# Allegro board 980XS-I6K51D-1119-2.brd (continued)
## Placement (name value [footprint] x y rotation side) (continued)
NOREF#777  -  []  348.03 289.54 0 top
NOREF#778  -  []  351.69 209.1 0 top
NOREF#779  -  []  457.43 161.06 0 top
NOREF#780  -  []  353.8 243.65 0 top
NOREF#781  -  []  481.73 253.51 0 top
NOREF#782  -  []  373.62 484.08 0 top
NOREF#783  -  []  100.39 154.45 0 top
NOREF#784  -  []  267.55 484.08 0 top
NOREF#785  -  []  223.27 174.06 0 top
NOREF#786  -  []  300.62 297.29 0 top
NOREF#787  -  []  332.33 182.3 90 top
NOREF#788  -  []  487.59 137.63 90 top
NOREF#789  -  []  227 259.15 0 top
NOREF#790  -  []  309.17 178.73 90 top
NOREF#791  -  []  479.53 221.76 0 top
NOREF#792  -  []  535.13 205.77 90 top
NOREF#793  -  []  350.87 210.03 90 top
NOREF#794  -  []  213.61 182 0 top
NOREF#795  -  []  352.23 230.19 90 top
NOREF#796  -  []  524.36 233.84 90 top
NOREF#797  -  []  474.48 169.9 0 top
NOREF#798  -  []  229.5 210 0 top
NOREF#799  -  []  226.84 148.23 90 top
NOREF#800  -  []  459.73 192.01 0 top
NOREF#801  -  []  232.7 190.05 0 top
NOREF#802  -  []  85 291.64 0 top
NOREF#803  -  []  309.83 269.1 90 top
NOREF#804  -  []  78.8 264.19 0 top
NOREF#805  -  []  304.91 233.9 0 top
NOREF#806  -  []  228.09 268.12 0 top
NOREF#807  -  []  310.5 190.23 90 top
NOREF#808  -  []  403.55 467.68 0 top
NOREF#809  -  []  223.09 172.9 0 top
NOREF#810  -  []  227.05 134.86 0 top
NOREF#811  -  []  210.61 235.6 90 top
NOREF#812  -  []  300.15 483.75 90 top
NOREF#813  -  []  99.29 220.75 0 top
NOREF#814  -  []  48.53 250.3 0 top
NOREF#815  -  []  275.44 194.76 90 top
NOREF#816  -  []  237.14 138.77 90 top
NOREF#817  -  []  490.86 199.63 90 top
NOREF#818  -  []  343.95 173.9 90 top
NOREF#819  -  []  349.53 181.46 90 top
NOREF#820  -  []  223.09 233.82 0 top
NOREF#821  -  []  311.8 250.23 90 top
NOREF#822  -  []  292.33 253.86 90 top
NOREF#823  -  []  393.34 467.08 0 top
NOREF#824  -  []  311.78 243.92 90 top
NOREF#825  -  []  310.92 244.4 0 top
NOREF#826  -  []  211.34 254.86 0 top
NOREF#827  -  []  122.2 484.32 0 top
NOREF#828  -  []  285.83 229.63 90 top
NOREF#829  -  []  540.03 233.63 90 top
NOREF#830  -  []  488.26 212.68 90 top
NOREF#831  -  []  262.45 231.5 0 top
NOREF#832  -  []  342.49 297.25 90 top
NOREF#833  -  []  349.53 240.81 90 top
NOREF#834  -  []  315.12 299.54 0 top
NOREF#835  -  []  260.96 235.55 90 top
NOREF#836  -  []  559.34 167.08 0 top
NOREF#837  -  []  345.33 135.72 0 top
NOREF#838  -  []  302.22 296.45 90 top
NOREF#839  -  []  317.44 253.76 90 top
NOREF#840  -  []  269.83 209.1 90 top
NOREF#841  -  []  458.53 190.01 0 top
NOREF#842  -  []  462.89 201.02 90 top
NOREF#843  -  []  273.49 295.27 90 top
NOREF#844  -  []  278.28 483.75 90 top
NOREF#845  -  []  292.33 182.3 90 top
NOREF#846  -  []  130.08 483.84 90 top
NOREF#847  -  []  481.53 160.91 90 top
NOREF#848  -  []  487.26 226.78 90 top
NOREF#849  -  []  37.98 484.08 0 top
NOREF#850  -  []  474.48 233.4 0 top
NOREF#851  -  []  313.4 298.37 0 top
NOREF#852  -  []  232.91 249.57 90 top
NOREF#853  -  []  142.1 483.84 90 top
NOREF#854  -  []  381.98 467.63 0 top
NOREF#855  -  []  310.87 210.03 90 top
NOREF#856  -  []  295.56 192.47 90 top
NOREF#857  -  []  356.15 189.57 90 top
NOREF#858  -  []  271.03 245.37 0 top
NOREF#859  -  []  279.68 483.76 90 top
NOREF#860  -  []  293.39 183.61 0 top
NOREF#861  -  []  468.26 170.15 0 top
NOREF#862  -  []  294.36 181.55 0 top
NOREF#863  -  []  270.16 244.72 90 top
NOREF#864  -  []  270.62 187.15 0 top
NOREF#865  -  []  226.61 190.23 90 top
NOREF#866  -  []  233.49 295.27 90 top
NOREF#867  -  []  230.75 241.59 0 top
NOREF#868  -  []  344.52 288.97 0 top
NOREF#869  -  []  356.89 133.69 0 top
NOREF#870  -  []  28.16 484.08 0 top
NOREF#871  -  []  148.26 484.32 0 top
NOREF#872  -  []  335.71 192.27 0 top
NOREF#873  -  []  227.71 189.57 90 top
NOREF#874  -  []  214.36 243.2 0 top
NOREF#875  -  []  291.83 230.23 315 top
NOREF#876  -  []  332.78 190.69 90 top
NOREF#877  -  []  265.48 235.27 0 top
NOREF#878  -  []  120.26 483.84 90 top
NOREF#879  -  []  362.33 173.13 90 top
NOREF#880  -  []  307.03 241.43 90 top
NOREF#881  -  []  215.56 252.47 90 top
NOREF#882  -  []  316.16 189.57 90 top
NOREF#883  -  []  268.52 244.61 90 top
NOREF#884  -  []  315.13 183 0 top
NOREF#885  -  []  254.3 250.94 90 top
NOREF#886  -  []  316.09 484.08 0 top
NOREF#887  -  []  476.48 161.06 0 top
NOREF#888  -  []  256.21 252.91 90 top
NOREF#889  -  []  242.3 484.08 0 top
NOREF#890  -  []  142.83 484.08 0 top
NOREF#891  -  []  272.25 189.57 90 top
NOREF#892  -  []  476.48 161.06 0 top
NOREF#893  -  []  527.08 484.08 0 top
NOREF#894  -  []  104.66 193.9 0 top
NOREF#895  -  []  261.29 297.9 0 top
NOREF#896  -  []  473.18 190.01 0 top
NOREF#897  -  []  227.03 241.43 90 top
NOREF#898  -  []  280.05 484.32 0 top
NOREF#899  -  []  254.38 183.29 0 top
NOREF#900  -  []  482.26 163.28 0 top
NOREF#901  -  []  269.11 232.64 90 top
NOREF#902  -  []  240.12 259.78 0 top
NOREF#903  -  []  294.68 195.18 0 top
NOREF#904  -  []  254.42 178.17 90 top
NOREF#905  -  []  87.37 286.27 90 top
NOREF#906  -  []  40.23 254.72 0 top
NOREF#907  -  []  253.61 242 0 top
NOREF#908  -  []  294.68 242.3 90 top
NOREF#909  -  []  347.56 144.79 0 top
NOREF#910  -  []  106.74 249.7 0 top
NOREF#911  -  []  351.48 186.02 90 top
NOREF#912  -  []  508.12 207 90 top
NOREF#913  -  []  305.97 484.4 0 top
NOREF#914  -  []  547.34 221.28 0 top
NOREF#915  -  []  231.03 185.37 0 top
NOREF#916  -  []  566.42 171.11 0 top
NOREF#917  -  []  353.17 296.17 0 top
NOREF#918  -  []  275.47 483.75 90 top
NOREF#919  -  []  138.62 484.08 0 top
NOREF#920  -  []  86.59 252.5 0 top
NOREF#921  -  []  254.3 179.37 90 top
NOREF#922  -  []  352.27 484.4 0 top
NOREF#923  -  []  211.16 191.72 0 top
NOREF#924  -  []  495.12 208.21 90 top
NOREF#925  -  []  335.23 483.75 90 top
NOREF#926  -  []  255.83 259.63 0 top
NOREF#927  -  []  275.81 182.28 90 top
NOREF#928  -  []  331.83 170.23 315 top
NOREF#929  -  []  381.68 462.53 90 top
NOREF#930  -  []  228.03 292.21 0 top
NOREF#931  -  []  104.34 252.35 90 top
NOREF#932  -  []  348.93 268.11 0 top
NOREF#933  -  []  215.71 242 90 top
NOREF#934  -  []  231.21 185.61 0 top
NOREF#935  -  []  331.64 243.61 0 top
NOREF#936  -  []  268.55 238.53 90 top
NOREF#937  -  []  347.9 182.43 90 top
NOREF#938  -  []  371.73 466.58 90 top
NOREF#939  -  []  122.38 484.08 0 top
NOREF#940  -  []  235.06 190.23 90 top
NOREF#941  -  []  291.83 170.23 315 top
NOREF#942  -  []  257.83 192.37 0 top
NOREF#943  -  []  289.83 225.63 90 top
NOREF#944  -  []  291.23 236.59 90 top
NOREF#945  -  []  475.5 134.21 0 top
NOREF#946  -  []  298.17 269.61 90 top
NOREF#947  -  []  232.57 246.5 0 top
NOREF#948  -  []  230.59 244.96 0 top
NOREF#949  -  []  110.89 186.2 0 top
NOREF#950  -  []  309.94 186.91 0 top
NOREF#951  -  []  344.96 136.11 90 top
NOREF#952  -  []  475.5 197.71 0 top
NOREF#953  -  []  488.26 244.43 90 top
NOREF#954  -  []  344.16 467.63 0 top
NOREF#955  -  []  83.29 217.95 0 top
NOREF#956  -  []  52.02 484.08 0 top
NOREF#957  -  []  354.92 467.68 0 top
NOREF#958  -  []  451.08 161.06 0 top
NOREF#959  -  []  235.44 194.76 90 top
NOREF#960  -  []  231.16 246.31 90 top
NOREF#961  -  []  349.26 462.53 90 top
NOREF#962  -  []  534.61 231.63 0 top
NOREF#963  -  []  134.41 484.08 0 top
NOREF#964  -  []  335.49 243.29 90 top
NOREF#965  -  []  255.1 274.12 0 top
NOREF#966  -  []  511.12 227.17 90 top
NOREF#967  -  []  212.96 243.2 0 top
NOREF#968  -  []  297.55 484.4 0 top
NOREF#969  -  []  59.94 196.2 0 top
NOREF#970  -  []  334.03 484.4 0 top
NOREF#971  -  []  340.81 187.17 90 top
NOREF#972  -  []  261.62 297 90 top
NOREF#973  -  []  568.79 147.98 0 top
NOREF#974  -  []  236.59 262.58 0 top
NOREF#975  -  []  232.23 167.99 90 top
NOREF#976  -  []  215.38 253.86 90 top
NOREF#977  -  []  85.29 220.6 90 top
NOREF#978  -  []  236.11 224.14 90 top
NOREF#979  -  []  351.26 247.56 0 top
NOREF#980  -  []  111.42 222.97 0 top
NOREF#981  -  []  49.56 267.3 90 top
NOREF#982  -  []  466.83 253.51 0 top
NOREF#983  -  []  367.5 483.75 90 top
NOREF#984  -  []  161.07 484.08 0 top
NOREF#985  -  []  346.91 146.64 0 top
NOREF#986  -  []  351.8 181.77 90 top
NOREF#987  -  []  541.61 164.49 0 top
NOREF#988  -  []  334.42 249.74 90 top
NOREF#989  -  []  361.57 134.52 90 top
NOREF#990  -  []  230.92 184.4 0 top
NOREF#991  -  []  104.34 188.85 90 top
NOREF#992  -  []  335.71 242 0 top
NOREF#993  -  []  232.45 183.76 90 top
NOREF#994  -  []  95.24 251.7 0 top
NOREF#995  -  []  294.42 238.17 90 top
NOREF#996  -  []  305.94 263.76 0 top
NOREF#997  -  []  39.39 484.08 0 top
NOREF#998  -  []  295.09 266.49 0 top
NOREF#999  -  []  365.77 467.63 0 top
NOREF#1000  -  []  313.08 240.67 90 top
NOREF#1001  -  []  457.43 224.56 0 top
NOREF#1002  -  []  265.33 135.72 0 top
NOREF#1003  -  []  304.52 287.7 90 top
NOREF#1004  -  []  252.7 271.22 0 top
NOREF#1005  -  []  310.62 247.15 0 top
NOREF#1006  -  []  253.86 192.91 90 top
NOREF#1007  -  []  293.54 239.12 90 top
NOREF#1008  -  []  23.95 484.08 0 top
NOREF#1009  -  []  522.5 149.61 0 top
NOREF#1010  -  []  231.81 179.17 90 top
NOREF#1011  -  []  333.99 253.86 90 top
NOREF#1012  -  []  348.71 463.08 90 top
NOREF#1013  -  []  483.26 140.63 0 top
NOREF#1014  -  []  214.81 181.35 90 top
NOREF#1015  -  []  293.54 250.69 90 top
NOREF#1016  -  []  540.03 233.63 0 top
NOREF#1017  -  []  86.2 277.28 90 top
NOREF#1018  -  []  304.87 484.08 0 top
NOREF#1019  -  []  15.54 484.08 0 top
NOREF#1020  -  []  131.48 483.84 90 top
NOREF#1021  -  []  360.04 135.47 90 top
NOREF#1022  -  []  268.01 234.3 90 top
NOREF#1023  -  []  480.26 169.28 90 top
NOREF#1024  -  []  271.48 246.66 90 top
NOREF#1025  -  []  268.44 262.36 0 top
NOREF#1026  -  []  104.54 154.45 0 top
NOREF#1027  -  []  303.95 233.9 90 top
NOREF#1028  -  []  474.12 240.61 0 top
NOREF#1029  -  []  254.81 181.35 90 top
NOREF#1030  -  []  267.75 232.44 90 top
NOREF#1031  -  []  230.13 207.46 90 top
NOREF#1032  -  []  265.43 295.89 90 top
NOREF#1033  -  []  310.59 240.4 0 top
NOREF#1034  -  []  308.01 174.3 90 top
NOREF#1035  -  []  315.81 242.28 90 top
NOREF#1036  -  []  230.41 180.16 0 top
NOREF#1037  -  []  236.52 134.86 0 top
NOREF#1038  -  []  353.8 183.65 0 top
NOREF#1039  -  []  335.56 240.9 90 top
NOREF#1040  -  []  331.16 187.72 90 top
NOREF#1041  -  []  361.04 135.78 0 top
NOREF#1042  -  []  314.61 297.98 90 top
NOREF#1043  -  []  280.83 157.63 90 top
NOREF#1044  -  []  117.99 484.32 0 top
NOREF#1045  -  []  225.29 172.02 90 top
NOREF#1046  -  []  222.22 296.45 90 top
NOREF#1047  -  []  227.41 133.69 0 top
NOREF#1048  -  []  308.67 181.95 0 top
NOREF#1049  -  []  255.16 251.22 90 top
NOREF#1050  -  []  343.27 174.62 0 top
NOREF#1051  -  []  272.66 483.75 90 top
NOREF#1052  -  []  503.71 228 0 top
NOREF#1053  -  []  268.93 208.11 0 top
NOREF#1054  -  []  254.36 241.55 0 top
NOREF#1055  -  []  43.09 483.76 90 top
NOREF#1056  -  []  335.01 193.56 0 top
NOREF#1057  -  []  213.29 242.3 90 top
NOREF#1058  -  []  271.89 184.89 90 top
NOREF#1059  -  []  237.11 164.14 90 top
NOREF#1060  -  []  473.18 158.26 0 top
NOREF#1061  -  []  332.54 182.65 90 top
NOREF#1062  -  []  269.94 246.26 0 top
NOREF#1063  -  []  141.42 484.08 0 top
NOREF#1064  -  []  260.96 175.55 90 top
NOREF#1065  -  []  346.74 298.45 0 top
NOREF#1066  -  []  245.95 273.47 0 top
NOREF#1067  -  []  394.66 484.08 0 top
NOREF#1068  -  []  419.5 462.53 90 top
NOREF#1069  -  []  354.91 224.78 0 top
NOREF#1070  -  []  16.44 483.76 90 top
NOREF#1071  -  []  335.71 180.7 0 top
NOREF#1072  -  []  255.71 252.27 0 top
NOREF#1073  -  []  313.4 299.38 0 top
NOREF#1074  -  []  474.12 145.36 0 top
NOREF#1075  -  []  485.88 158.26 0 top
NOREF#1076  -  []  238.39 141.02 0 top
NOREF#1077  -  []  272.35 292.46 90 top
NOREF#1078  -  []  311.21 185.61 0 top
NOREF#1079  -  []  220.96 187.12 90 top
NOREF#1080  -  []  272.05 178.99 0 top
NOREF#1081  -  []  272.23 170.19 90 top
NOREF#1082  -  []  111.42 127.72 0 top
NOREF#1083  -  []  349.94 246.91 0 top
NOREF#1084  -  []  304.47 291.41 90 top
NOREF#1085  -  []  275.13 183 0 top
NOREF#1086  -  []  83.67 262.04 0 top
NOREF#1087  -  []  227.99 241.7 0 top
NOREF#1088  -  []  270.5 190.23 90 top
NOREF#1089  -  []  231.11 296.5 90 top
NOREF#1090  -  []  295.83 199.63 0 top
NOREF#1091  -  []  232.05 238.99 0 top
NOREF#1092  -  []  335.58 242.65 90 top
NOREF#1093  -  []  317.14 138.77 90 top
NOREF#1094  -  []  276.11 224.14 90 top
NOREF#1095  -  []  359.1 142.99 90 top
NOREF#1096  -  []  110.69 252.35 90 top
NOREF#1097  -  []  223.27 234.06 0 top
NOREF#1098  -  []  295.83 259.63 0 top
NOREF#1099  -  []  352.57 184.24 90 top
NOREF#1100  -  []  457.43 161.06 0 top
NOREF#1101  -  []  280.04 140.12 0 top
NOREF#1102  -  []  358.39 141.02 0 top
NOREF#1103  -  []  232.8 247.31 90 top
NOREF#1104  -  []  306.54 134.31 90 top
NOREF#1105  -  []  304.36 483.75 90 top
NOREF#1106  -  []  352.9 189.57 90 top
NOREF#1107  -  []  349.23 268.44 0 top
NOREF#1108  -  []  332.78 239.12 90 top
NOREF#1109  -  []  85.83 238.84 90 top
NOREF#1110  -  []  295.51 252.91 90 top
NOREF#1111  -  []  506.6 226.11 90 top
NOREF#1112  -  []  265.33 133.69 0 top
NOREF#1113  -  []  332.66 182 0 top
NOREF#1114  -  []  233.73 183.95 90 top
NOREF#1115  -  []  251.96 253.56 0 top
NOREF#1116  -  []  335.38 182.3 90 top
NOREF#1117  -  []  357.88 484.4 0 top
NOREF#1118  -  []  331.83 230.23 315 top
NOREF#1119  -  []  349.11 172.64 90 top
NOREF#1120  -  []  334.68 242.3 90 top
NOREF#1121  -  []  534.61 220.08 0 top
NOREF#1122  -  []  321.7 484.08 0 top
NOREF#1123  -  []  114.42 234.57 0 top
NOREF#1124  -  []  308.31 239.21 0 top
NOREF#1125  -  []  274.95 242.76 0 top
NOREF#1126  -  []  225.44 146.16 90 top
NOREF#1127  -  []  352.45 190.23 90 top
NOREF#1128  -  []  475.5 165.96 0 top
NOREF#1129  -  []  351.27 185.2 0 top
NOREF#1130  -  []  493.02 145.03 0 top
NOREF#1131  -  []  240.9 484.08 0 top
NOREF#1132  -  []  452.74 2.28 90 top
NOREF#1133  -  []  230.87 210.03 90 top
NOREF#1134  -  []  487.59 232.88 90 top
NOREF#1135  -  []  365.47 462.53 90 top
NOREF#1136  -  []  533.93 205.02 0 top
NOREF#1137  -  []  487.26 195.03 90 top
NOREF#1138  -  []  227.65 261.5 90 top
NOREF#1139  -  []  470.13 224.56 0 top
NOREF#1140  -  []  351.88 184.89 90 top
NOREF#1141  -  []  488.08 158.26 0 top
NOREF#1142  -  []  92.33 228.96 90 top
NOREF#1143  -  []  217.83 252.37 0 top
NOREF#1144  -  []  477.58 253.51 0 top
NOREF#1145  -  []  255.49 194.86 90 top
NOREF#1146  -  []  540.03 220.67 90 top
NOREF#1147  -  []  30.97 484.08 0 top
NOREF#1148  -  []  80.69 287.44 90 top
NOREF#1149  -  []  274.21 189.57 90 top
NOREF#1150  -  []  315.21 285.21 90 top
NOREF#1151  -  []  310.57 210.84 0 top
NOREF#1152  -  []  229.11 173.64 90 top
NOREF#1153  -  []  411.2 484.4 0 top
NOREF#1154  -  []  347.7 189.57 90 top
NOREF#1155  -  []  310.59 244.96 0 top
NOREF#1156  -  []  231.27 179.68 90 top
NOREF#1157  -  []  312.91 178.51 90 top
NOREF#1158  -  []  80.94 278.6 0 top
NOREF#1159  -  []  224.47 291.41 90 top
NOREF#1160  -  []  380.13 483.75 90 top
NOREF#1161  -  []  261.82 296.65 90 top
NOREF#1162  -  []  110.89 217.95 0 top
NOREF#1163  -  []  270.57 270.84 0 top
NOREF#1164  -  []  269.01 181.77 90 top
NOREF#1165  -  []  253.61 193.56 0 top
NOREF#1166  -  []  473.18 221.76 0 top
NOREF#1167  -  []  551.91 149.79 0 top
NOREF#1168  -  []  474.12 208.86 0 top
NOREF#1169  -  []  310.47 244.57 90 top
NOREF#1170  -  []  478.69 166.11 90 top
NOREF#1171  -  []  310.5 181.77 90 top
NOREF#1172  -  []  23.45 483.76 90 top
NOREF#1173  -  []  104.34 220.6 90 top
NOREF#1174  -  []  269.53 240.81 90 top
NOREF#1175  -  []  231.15 250.23 90 top
NOREF#1176  -  []  313.81 243.65 0 top
NOREF#1177  -  []  377.83 484.08 0 top
NOREF#1178  -  []  271.76 484.08 0 top
NOREF#1179  -  []  315.23 223.88 90 top
NOREF#1180  -  []  45.98 272.89 0 top
NOREF#1181  -  []  105.64 189 0 top
NOREF#1182  -  []  229.3 245.2 0 top
NOREF#1183  -  []  91.84 186.2 0 top
NOREF#1184  -  []  238.37 259.8 0 top
NOREF#1185  -  []  271.71 244.72 0 top
NOREF#1186  -  []  231.48 186.02 90 top
NOREF#1187  -  []  345.48 175.27 0 top
NOREF#1188  -  []  349.57 467.63 0 top
NOREF#1189  -  []  55.64 248.1 0 top
NOREF#1190  -  []  308.03 289.54 0 top
NOREF#1191  -  []  123.08 170.76 0 top
NOREF#1192  -  []  227.91 244.41 90 top
NOREF#1193  -  []  86.59 252.5 0 top
NOREF#1194  -  []  254.66 241.23 0 top
NOREF#1195  -  []  95.99 186.2 0 top
NOREF#1196  -  []  335.16 179.65 90 top
NOREF#1197  -  []  231.94 247.8 0 top
NOREF#1198  -  []  365.83 169.63 90 top
NOREF#1199  -  []  473.22 145.03 0 top
NOREF#1200  -  []  108.69 249.7 0 top
NOREF#1201  -  []  231.4 186.13 0 top
NOREF#1202  -  []  215.16 191.22 90 top
NOREF#1203  -  []  346.91 141.04 90 top
NOREF#1204  -  []  237.14 141.43 90 top
NOREF#1205  -  []  122.64 246.5 90 top
NOREF#1206  -  []  270.13 267.46 90 top
NOREF#1207  -  []  317.19 484.4 0 top
NOREF#1208  -  []  219.33 196.13 0 top
NOREF#1209  -  []  352.45 180.47 90 top
NOREF#1210  -  []  270.41 180.16 0 top
NOREF#1211  -  []  270.82 240.82 90 top
NOREF#1212  -  []  154.73 483.84 90 top
NOREF#1213  -  []  506.92 207.65 0 top
NOREF#1214  -  []  215.83 259.63 0 top
NOREF#1215  -  []  539.84 220.37 0 top
NOREF#1216  -  []  334.38 194.86 0 top
NOREF#1217  -  []  238.7 260.1 90 top
NOREF#1218  -  []  311.38 483.75 90 top
NOREF#1219  -  []  295.76 252.32 0 top
NOREF#1220  -  []  339.33 256.13 0 top
NOREF#1221  -  []  487.88 192.66 90 top
NOREF#1222  -  []  310.01 210.51 0 top
NOREF#1223  -  []  236.89 133.69 0 top
NOREF#1224  -  []  313.29 484.08 0 top
NOREF#1225  -  []  351.08 269.73 0 top
NOREF#1226  -  []  316.61 288.05 0 top
NOREF#1227  -  []  460.48 158.26 0 top
NOREF#1228  -  []  233.35 190.05 0 top
NOREF#1229  -  []  485.88 253.51 0 top
NOREF#1230  -  []  85.29 157.1 90 top
NOREF#1231  -  []  119.44 217.95 0 top
NOREF#1232  -  []  228.15 182.25 0 top
NOREF#1233  -  []  72.69 293.24 0 top
NOREF#1234  -  []  129.4 484.08 0 top
NOREF#1235  -  []  549.55 154.21 0 top
NOREF#1236  -  []  111.99 220.75 0 top
NOREF#1237  -  []  547.34 234.23 0 top
NOREF#1238  -  []  227.25 234.3 90 top
NOREF#1239  -  []  309.11 233.64 90 top
NOREF#1240  -  []  408.15 463.08 90 top
NOREF#1241  -  []  89.64 217.95 0 top
NOREF#1242  -  []  79.1 291.94 0 top
NOREF#1243  -  []  317.95 143.66 90 top
NOREF#1244  -  []  295.58 254.22 90 top
NOREF#1245  -  []  371.23 176.59 90 top
NOREF#1246  -  []  240.83 217.63 90 top
NOREF#1247  -  []  267.56 144.79 0 top
NOREF#1248  -  []  275.44 254.76 90 top
NOREF#1249  -  []  105.64 252.5 0 top
NOREF#1250  -  []  548.24 234.56 0 top
NOREF#1251  -  []  291.34 254.86 0 top
NOREF#1252  -  []  293.86 241.35 90 top
NOREF#1253  -  []  275.23 223.88 90 top
NOREF#1254  -  []  350.91 244.4 0 top
NOREF#1255  -  []  310.92 184.4 0 top
NOREF#1256  -  []  227 262.2 0 top
NOREF#1257  -  []  102.24 161.14 90 top
NOREF#1258  -  []  334.3 250.94 90 top
NOREF#1259  -  []  213.29 253.86 90 top
NOREF#1260  -  []  475.38 221.76 0 top
NOREF#1261  -  []  221.62 297 90 top
NOREF#1262  -  []  237.12 260.2 0 top
NOREF#1263  -  []  310.74 250.05 0 top
NOREF#1264  -  []  119.58 484.08 0 top
NOREF#1265  -  []  231.61 181.11 90 top
NOREF#1266  -  []  38.35 196.2 0 top
NOREF#1267  -  []  228.49 136.9 0 top
NOREF#1268  -  []  105.64 189 0 top
NOREF#1269  -  []  111.99 189 0 top
NOREF#1270  -  []  315.44 194.76 90 top
NOREF#1271  -  []  305.48 173.73 90 top
NOREF#1272  -  []  267.05 134.86 0 top
NOREF#1273  -  []  343.92 299.38 0 top
NOREF#1274  -  []  295.01 182 0 top
NOREF#1275  -  []  276.16 189.57 90 top
NOREF#1276  -  []  304.09 232.66 0 top
NOREF#1277  -  []  278.57 171.63 90 top
NOREF#1278  -  []  352.45 240.47 90 top
NOREF#1279  -  []  231.19 209.1 90 top
NOREF#1280  -  []  410.1 484.08 0 top
NOREF#1281  -  []  399.98 484.4 0 top
NOREF#1282  -  []  293.54 179.12 90 top
NOREF#1283  -  []  346.84 148.23 90 top
NOREF#1284  -  []  306.84 250.05 0 top
NOREF#1285  -  []  234.82 284.84 90 top
NOREF#1286  -  []  308.52 244.61 90 top
NOREF#1287  -  []  277.44 253.76 90 top
NOREF#1288  -  []  351.39 190.05 0 top
NOREF#1289  -  []  549.44 233.91 90 top
NOREF#1290  -  []  302.96 483.75 90 top
NOREF#1291  -  []  349.04 201.34 90 top
NOREF#1292  -  []  234.97 145.37 90 top
NOREF#1293  -  []  281.34 136.1 0 top
NOREF#1294  -  []  458.37 212.88 0 top
NOREF#1295  -  []  115.04 186.2 0 top
NOREF#1296  -  []  270.74 250.05 0 top
NOREF#1297  -  []  512.28 223.9 90 top
NOREF#1298  -  []  363.5 484.4 0 top
NOREF#1299  -  []  334.38 254.86 0 top
NOREF#1300  -  []  86.59 189 0 top
NOREF#1301  -  []  231.16 241.77 90 top
NOREF#1302  -  []  269.94 185.61 0 top
NOREF#1303  -  []  229.53 180.81 90 top
NOREF#1304  -  []  309.96 181.3 0 top
NOREF#1305  -  []  311.48 245.37 90 top
NOREF#1306  -  []  310.59 184.96 0 top
NOREF#1307  -  []  394.36 484.4 0 top
NOREF#1308  -  []  273.99 208.8 0 top
NOREF#1309  -  []  122.18 172.97 0 top
NOREF#1310  -  []  161.75 483.84 90 top
NOREF#1311  -  []  348.52 184.61 90 top
NOREF#1312  -  []  343.27 175.18 0 top
NOREF#1313  -  []  22.55 484.08 0 top
NOREF#1314  -  []  261.84 204.24 0 top
NOREF#1315  -  []  232.91 181.11 90 top
NOREF#1316  -  []  357.11 164.14 90 top
NOREF#1317  -  []  351.12 243.92 90 top
NOREF#1318  -  []  387.35 484.4 0 top
NOREF#1319  -  []  338.17 269.61 90 top
NOREF#1320  -  []  306.63 181.83 90 top
NOREF#1321  -  []  251.34 243.29 0 top
NOREF#1322  -  []  333.61 242 0 top
NOREF#1323  -  []  277.14 138.77 90 top
NOREF#1324  -  []  300.81 235.6 90 top
NOREF#1325  -  []  313.63 140.86 0 top
NOREF#1326  -  []  308.67 181.3 0 top
NOREF#1327  -  []  271.81 241.77 90 top
NOREF#1328  -  []  228.01 174.3 90 top
NOREF#1329  -  []  273.66 269.1 90 top
NOREF#1330  -  []  48.91 484.4 0 top
NOREF#1331  -  []  305.33 134.7 0 top
NOREF#1332  -  []  365.52 462.48 90 top
NOREF#1333  -  []  535.13 207.16 90 top
NOREF#1334  -  []  351.69 269.1 0 top
NOREF#1335  -  []  276.23 130.83 90 top
NOREF#1336  -  []  271.78 243.92 90 top
NOREF#1337  -  []  568.79 150.18 0 top
NOREF#1338  -  []  495.12 173.92 90 top
NOREF#1339  -  []  215.01 182 0 top
NOREF#1340  -  []  352.23 232.39 90 top
NOREF#1341  -  []  350.62 246.5 0 top
NOREF#1342  -  []  304.52 286.43 0 top
NOREF#1343  -  []  213.09 255.5 0 top
NOREF#1344  -  []  314.75 286.43 0 top
NOREF#1345  -  []  355.91 224.78 0 top
NOREF#1346  -  []  347.9 242.43 90 top
NOREF#1347  -  []  331.64 255.18 0 top
NOREF#1348  -  []  264.91 173.9 0 top
NOREF#1349  -  []  271.81 239.17 90 top
NOREF#1350  -  []  348.01 173.3 90 top
NOREF#1351  -  []  213.54 250.69 90 top
NOREF#1352  -  []  59.94 142.86 0 top
NOREF#1353  -  []  353.62 243.41 0 top
NOREF#1354  -  []  103.28 170.76 0 top
NOREF#1355  -  []  236.7 297.74 0 top
NOREF#1356  -  []  312.87 244.43 0 top
NOREF#1357  -  []  343.95 172.42 90 top
NOREF#1358  -  []  387.34 467.68 0 top
NOREF#1359  -  []  475.5 229.46 0 top
NOREF#1360  -  []  525.37 484.4 0 top
NOREF#1361  -  []  240.04 137.42 90 top
NOREF#1362  -  []  116.05 483.84 90 top
NOREF#1363  -  []  334.36 193.12 0 top
NOREF#1364  -  []  276.87 483.75 90 top
NOREF#1365  -  []  289.43 484.08 0 top
NOREF#1366  -  []  466.08 192.01 0 top
NOREF#1367  -  []  361.34 136.1 0 top
NOREF#1368  -  []  86.2 262.11 90 top
NOREF#1369  -  []  254.68 253.86 90 top
NOREF#1370  -  []  121.66 483.84 90 top
NOREF#1371  -  []  343.09 173.82 0 top
NOREF#1372  -  []  356.11 164.14 90 top
NOREF#1373  -  []  264.52 290.37 90 top
NOREF#1374  -  []  307.05 135.87 0 top
NOREF#1375  -  []  85.49 186.2 0 top
NOREF#1376  -  []  239.47 259.85 90 top
NOREF#1377  -  []  356.78 484.08 0 top
NOREF#1378  -  []  291.96 253.56 0 top
NOREF#1379  -  []  253.02 483.75 90 top
NOREF#1380  -  []  533.93 206.42 0 top
NOREF#1381  -  []  95.99 186.2 0 top
NOREF#1382  -  []  544.41 149.79 90 top
NOREF#1383  -  []  214.29 195.5 0 top
NOREF#1384  -  []  493.48 218.56 90 top
NOREF#1385  -  []  541.61 166.69 0 top
NOREF#1386  -  []  271.81 179.17 90 top
NOREF#1387  -  []  122.18 170.43 0 top
NOREF#1388  -  []  271.19 209.1 90 top
NOREF#1389  -  []  254.68 182.3 90 top
NOREF#1390  -  []  215.71 182 0 top
NOREF#1391  -  []  458.37 244.63 0 top
NOREF#1392  -  []  102.24 129.39 90 top
NOREF#1393  -  []  310.55 134.62 0 top
NOREF#1394  -  []  314.21 189.57 90 top
NOREF#1395  -  []  268.01 174.3 90 top
NOREF#1396  -  []  253.54 250.69 90 top
NOREF#1397  -  []  226.45 147.01 90 top
NOREF#1398  -  []  294.81 252.91 90 top
NOREF#1399  -  []  91.22 275.47 90 top
NOREF#1400  -  []  228.62 185.61 0 top
NOREF#1401  -  []  305.14 298.99 90 top
NOREF#1402  -  []  540.55 206.94 0 top
NOREF#1403  -  []  271.48 185.37 90 top
NOREF#1404  -  []  309.11 173.64 90 top
NOREF#1405  -  []  546.96 207.94 0 top
NOREF#1406  -  []  306.54 133.3 90 top
NOREF#1407  -  []  83.21 273.81 90 top
NOREF#1408  -  []  102.34 154.45 0 top
NOREF#1409  -  []  265.14 298.99 90 top
NOREF#1410  -  []  303.27 175.18 0 top
NOREF#1411  -  []  563.28 170.72 90 top
NOREF#1412  -  []  47.98 268.08 0 top
NOREF#1413  -  []  309.11 232.64 90 top
NOREF#1414  -  []  516.36 239.64 0 top
NOREF#1415  -  []  223.09 234.94 0 top
NOREF#1416  -  []  40.65 247.71 90 top
NOREF#1417  -  []  231.69 209.1 0 top
NOREF#1418  -  []  232.91 241.11 90 top
NOREF#1419  -  []  113.78 484.32 0 top
NOREF#1420  -  []  560.49 171.11 0 top
NOREF#1421  -  []  352.23 167.99 0 top
NOREF#1422  -  []  545.19 154.99 0 top
NOREF#1423  -  []  468.83 256.16 90 top
NOREF#1424  -  []  249.01 484.4 0 top
NOREF#1425  -  []  270.92 244.4 0 top
NOREF#1426  -  []  341.84 264.24 0 top
NOREF#1427  -  []  317.49 484.08 0 top
NOREF#1428  -  []  251.96 242 0 top
NOREF#1429  -  []  458.65 181.13 0 top
NOREF#1430  -  []  347.75 232.44 90 top
NOREF#1431  -  []  225.68 261.06 90 top
NOREF#1432  -  []  271.89 244.96 0 top
NOREF#1433  -  []  308.31 179.21 0 top
NOREF#1434  -  []  216.91 181.35 90 top
NOREF#1435  -  []  85 265.66 0 top
NOREF#1436  -  []  291.16 251.72 0 top
NOREF#1437  -  []  348.55 178.53 90 top
NOREF#1438  -  []  493.48 250.31 90 top
NOREF#1439  -  []  313.35 190.05 0 top
NOREF#1440  -  []  272.23 167.99 90 top
NOREF#1441  -  []  272.2 286.98 90 top
NOREF#1442  -  []  459.73 160.26 0 top
NOREF#1443  -  []  360.92 467.08 0 top
NOREF#1444  -  []  252.66 193.56 0 top
NOREF#1445  -  []  303.95 172.42 90 top
NOREF#1446  -  []  158.94 483.84 90 top
NOREF#1447  -  []  269.04 201.34 90 top
NOREF#1448  -  []  40.65 249.91 90 top
NOREF#1449  -  []  29.27 484.4 0 top
NOREF#1450  -  []  285.83 169.63 90 top
NOREF#1451  -  []  366.1 483.75 90 top
NOREF#1452  -  []  277.95 135.78 90 top
NOREF#1453  -  []  458.37 244.63 0 top
NOREF#1454  -  []  19.74 484.08 0 top
NOREF#1455  -  []  506.6 207.95 90 top
NOREF#1456  -  []  344.52 286.43 0 top
NOREF#1457  -  []  353.99 208.8 0 top
NOREF#1458  -  []  238.82 259.15 0 top
NOREF#1459  -  []  353.34 190.05 0 top
NOREF#1460  -  []  250.21 483.75 90 top
NOREF#1461  -  []  292.66 182 0 top
NOREF#1462  -  []  114.29 156.45 0 top
NOREF#1463  -  []  255.76 180.75 0 top
NOREF#1464  -  []  468.83 192.66 90 top
NOREF#1465  -  []  254.38 243.29 0 top
NOREF#1466  -  []  258.17 269.61 90 top
NOREF#1467  -  []  300.67 292.95 0 top
NOREF#1468  -  []  247.91 484.08 0 top
NOREF#1469  -  []  235.69 268.12 90 top
NOREF#1470  -  []  228.01 173.3 90 top
NOREF#1471  -  []  311.6 241.11 90 top
NOREF#1472  -  []  103.59 246.5 90 top
NOREF#1473  -  []  240.76 262.82 90 top
NOREF#1474  -  []  313.11 243.75 90 top
NOREF#1475  -  []  353.07 183.95 90 top
NOREF#1476  -  []  113.96 484.08 0 top
NOREF#1477  -  []  296.21 252.91 90 top
NOREF#1478  -  []  390.46 484.08 0 top
NOREF#1479  -  []  233.11 190.23 90 top
NOREF#1480  -  []  231.81 241.77 90 top
NOREF#1481  -  []  19.24 483.76 90 top
NOREF#1482  -  []  478.78 160.26 0 top
NOREF#1483  -  []  273.81 243.65 0 top
NOREF#1484  -  []  123.61 484.32 0 top
NOREF#1485  -  []  272.8 247.31 90 top
NOREF#1486  -  []  116.75 133.82 90 top
NOREF#1487  -  []  307.56 144.79 0 top
NOREF#1488  -  []  335.09 201.99 90 top
NOREF#1489  -  []  273.08 180.67 90 top
NOREF#1490  -  []  334.81 252.91 90 top
NOREF#1491  -  []  215.58 182.65 90 top
NOREF#1492  -  []  398.74 467.08 0 top
NOREF#1493  -  []  271.15 190.23 90 top
NOREF#1494  -  []  346.33 150.83 0 top
NOREF#1495  -  []  275.91 164.78 0 top
NOREF#1496  -  []  343.95 174.46 90 top
NOREF#1497  -  []  547.86 212.46 0 top
NOREF#1498  -  []  276.7 296.96 90 top
NOREF#1499  -  []  352.45 183.76 90 top
NOREF#1500  -  []  231.78 243.92 90 top
NOREF#1501  -  []  231.4 246.12 0 top
NOREF#1502  -  []  38.89 268.86 0 top
NOREF#1503  -  []  213.54 190.69 90 top
NOREF#1504  -  []  92.94 252.5 0 top
NOREF#1505  -  []  323.96 287.7 90 top
NOREF#1506  -  []  265.29 172.02 90 top
NOREF#1507  -  []  397.34 463.08 90 top
NOREF#1508  -  []  307.17 483.75 90 top
NOREF#1509  -  []  345.05 146.58 0 top
NOREF#1510  -  []  309.33 270.27 0 top
NOREF#1511  -  []  231.27 245.2 0 top
NOREF#1512  -  []  253.29 182.3 90 top
NOREF#1513  -  []  232.87 244.43 0 top
NOREF#1514  -  []  109.94 151.25 90 top
NOREF#1515  -  []  231.78 183.92 90 top
NOREF#1516  -  []  263.95 173.9 90 top
NOREF#1517  -  []  346.63 187.43 0 top
NOREF#1518  -  []  101.59 219.95 0 top
NOREF#1519  -  []  331.64 195.18 0 top
NOREF#1520  -  []  77.67 261.24 0 top
NOREF#1521  -  []  263.27 234.06 0 top
NOREF#1522  -  []  288.93 483.75 90 top
NOREF#1523  -  []  469.03 190.01 0 top
NOREF#1524  -  []  348.31 239.21 0 top
NOREF#1525  -  []  357.95 138.45 90 top
NOREF#1526  -  []  347.57 245.37 90 top
NOREF#1527  -  []  351.89 244.96 0 top
NOREF#1528  -  []  505.85 229.95 0 top
NOREF#1529  -  []  461.73 250.31 90 top
NOREF#1530  -  []  210.56 235.55 90 top
NOREF#1531  -  []  345.94 263.76 0 top
NOREF#1532  -  []  230.62 186.5 0 top
NOREF#1533  -  []  87.81 132.56 90 top
NOREF#1534  -  []  124.47 483.84 90 top
NOREF#1535  -  []  229.11 233.64 90 top
NOREF#1536  -  []  335.49 194.86 90 top
NOREF#1537  -  []  115.04 217.95 0 top
NOREF#1538  -  []  291.96 182 0 top
NOREF#1539  -  []  232.57 184.24 90 top
NOREF#1540  -  []  268.66 484.4 0 top
NOREF#1541  -  []  291.96 242 0 top
NOREF#1542  -  []  350.82 180.82 90 top
NOREF#1543  -  []  558.12 150.18 0 top
NOREF#1544  -  []  233.63 140.86 0 top
NOREF#1545  -  []  40.47 268.08 90 top
NOREF#1546  -  []  149.66 484.32 0 top
NOREF#1547  -  []  363.29 483.75 90 top
NOREF#1548  -  []  117.04 157.1 90 top
NOREF#1549  -  []  225.48 235.27 0 top
NOREF#1550  -  []  109.94 183 90 top
NOREF#1551  -  []  232.87 184.43 0 top
NOREF#1552  -  []  350.26 184.4 0 top
NOREF#1553  -  []  265.44 146.16 90 top
NOREF#1554  -  []  270.74 241.59 0 top
NOREF#1555  -  []  485.26 174.88 0 top
NOREF#1556  -  []  312.57 186.5 0 top
NOREF#1557  -  []  111.99 220.75 0 top
NOREF#1558  -  []  311.48 186.02 90 top
NOREF#1559  -  []  115.81 278.82 90 top
NOREF#1560  -  []  215.58 194.22 90 top
NOREF#1561  -  []  336.21 181.35 90 top
NOREF#1562  -  []  332.66 242 0 top
NOREF#1563  -  []  270.5 241.77 90 top
NOREF#1564  -  []  378.93 484.4 0 top
NOREF#1565  -  []  232.22 183.1 0 top
NOREF#1566  -  []  376.12 484.4 0 top
NOREF#1567  -  []  350.41 240.16 0 top
NOREF#1568  -  []  512.28 205.74 90 top
NOREF#1569  -  []  295.09 261.99 90 top
NOREF#1570  -  []  226.33 150.83 0 top
NOREF#1571  -  []  285.22 484.08 0 top
NOREF#1572  -  []  307.66 245.09 0 top
NOREF#1573  -  []  254.38 254.86 0 top
NOREF#1574  -  []  295.01 193.56 0 top
NOREF#1575  -  []  487.26 163.28 90 top
NOREF#1576  -  []  212.33 193.86 90 top
NOREF#1577  -  []  303.09 174.38 0 top
NOREF#1578  -  []  309.61 185.05 0 top
NOREF#1579  -  []  350.87 270.03 90 top
NOREF#1580  -  []  103.64 229.59 0 top
NOREF#1581  -  []  249.83 203.63 90 top
NOREF#1582  -  []  347.99 181.06 0 top
NOREF#1583  -  []  292.66 253.56 0 top
NOREF#1584  -  []  224.24 207.14 0 top
NOREF#1585  -  []  295.38 182.3 90 top
NOREF#1586  -  []  97.42 229.84 0 top
NOREF#1587  -  []  331.16 240.15 0 top
NOREF#1588  -  []  282.54 140.92 0 top
NOREF#1589  -  []  482.83 224.56 0 top
NOREF#1590  -  []  272.46 180.47 90 top
NOREF#1591  -  []  49.74 246.93 90 top
NOREF#1592  -  []  292.66 242 0 top
NOREF#1593  -  []  267.05 134.08 90 top
NOREF#1594  -  []  296.21 192.91 90 top
NOREF#1595  -  []  308.67 241.29 0 top
NOREF#1596  -  []  274.23 247.83 0 top
NOREF#1597  -  []  331.16 191.72 0 top
NOREF#1598  -  []  213.22 251.59 0 top
NOREF#1599  -  []  320.83 217.63 90 top
NOREF#1600  -  []  331.16 236.15 90 top
NOREF#1601  -  []  264.45 484.4 0 top
NOREF#1602  -  []  308.25 234.12 0 top
NOREF#1603  -  []  263.27 292.05 0 top
NOREF#1604  -  []  343.95 173.34 90 top
NOREF#1605  -  []  360.69 484.4 0 top
NOREF#1606  -  []  253.16 192.91 90 top
NOREF#1607  -  []  488.26 149.18 90 top
NOREF#1608  -  []  103.64 197.84 0 top
NOREF#1609  -  []  225.88 175.27 0 top
NOREF#1610  -  []  95.24 188.2 0 top
NOREF#1611  -  []  274.95 182.76 0 top
NOREF#1612  -  []  236.16 189.57 90 top
NOREF#1613  -  []  313.99 208.8 0 top
NOREF#1614  -  []  271.12 243.92 90 top
NOREF#1615  -  []  458.75 142.24 90 top
NOREF#1616  -  []  239.77 260.68 0 top
NOREF#1617  -  []  214.31 182 0 top
NOREF#1618  -  []  356.22 286.06 90 top
NOREF#1619  -  []  267.25 173.9 90 top
NOREF#1620  -  []  535.51 217.71 90 top
NOREF#1621  -  []  293.16 252.91 90 top
NOREF#1622  -  []  270.59 240.4 0 top
NOREF#1623  -  []  88.89 251.7 0 top
NOREF#1624  -  []  254.68 183.61 0 top
NOREF#1625  -  []  459.73 255.51 0 top
NOREF#1626  -  []  312.23 172.39 90 top
NOREF#1627  -  []  261.84 264.24 0 top
NOREF#1628  -  []  228.62 245.61 0 top
NOREF#1629  -  []  309.98 483.75 90 top
NOREF#1630  -  []  351.78 243.92 90 top
NOREF#1631  -  []  295.38 193.86 90 top
NOREF#1632  -  []  350.59 184.96 0 top
NOREF#1633  -  []  481.73 190.01 0 top
NOREF#1634  -  []  262.22 296.45 90 top
NOREF#1635  -  []  32.07 484.4 0 top
NOREF#1636  -  []  293.61 193.56 0 top
NOREF#1637  -  []  364.7 483.75 90 top
NOREF#1638  -  []  231.61 249.57 90 top
NOREF#1639  -  []  265.88 175.27 0 top
NOREF#1640  -  []  292.78 250.69 90 top
NOREF#1641  -  []  404.49 484.08 0 top
NOREF#1642  -  []  106.74 154.45 0 top
NOREF#1643  -  []  346.54 135.09 0 top
NOREF#1644  -  []  107.85 130.55 90 top
NOREF#1645  -  []  269.33 270.27 0 top
NOREF#1646  -  []  460.48 253.51 0 top
NOREF#1647  -  []  104.54 186.2 0 top
NOREF#1648  -  []  466.83 190.01 0 top
NOREF#1649  -  []  102.34 249.7 0 top
NOREF#1650  -  []  264.52 288.97 0 top
NOREF#1651  -  []  457.43 256.31 0 top
NOREF#1652  -  []  475.32 205.67 90 top
NOREF#1653  -  []  547.86 211.06 0 top
NOREF#1654  -  []  334.42 189.74 90 top
NOREF#1655  -  []  128.92 417.57 90 top
NOREF#1656  -  []  535.51 230.66 90 top
NOREF#1657  -  []  276.16 249.57 90 top
NOREF#1658  -  []  271.16 243.72 90 top
NOREF#1659  -  []  332.66 253.56 0 top
NOREF#1660  -  []  104.48 170.11 90 top
NOREF#1661  -  []  354.75 285.63 90 top
NOREF#1662  -  []  294.66 192.79 0 top
NOREF#1663  -  []  272.9 189.57 90 top
NOREF#1664  -  []  353.07 243.95 90 top
NOREF#1665  -  []  345.48 233.73 90 top
NOREF#1666  -  []  80.24 157.25 0 top
NOREF#1667  -  []  254.29 255.5 0 top
NOREF#1668  -  []  255.09 266.49 0 top
NOREF#1669  -  []  304.24 267.14 0 top
NOREF#1670  -  []  352.23 227.99 90 top
NOREF#1671  -  []  315.44 194.76 90 top
NOREF#1672  -  []  294.38 243.29 0 top
NOREF#1673  -  []  310.62 246.5 0 top
NOREF#1674  -  []  353.07 240.67 90 top
NOREF#1675  -  []  102.36 161.62 90 top
NOREF#1676  -  []  102.36 129.87 90 top
NOREF#1677  -  []  333.29 182.3 90 top
NOREF#1678  -  []  122.64 151.25 90 top
NOREF#1679  -  []  304.42 236.56 0 top
NOREF#1680  -  []  404.19 484.4 0 top
NOREF#1681  -  []  399.77 483.75 90 top
NOREF#1682  -  []  413.55 463.08 90 top
NOREF#1683  -  []  259.14 484.08 0 top
NOREF#1684  -  []  79.1 278.23 0 top
NOREF#1685  -  []  462.68 253.51 0 top
NOREF#1686  -  []  63.57 254.33 0 top
NOREF#1687  -  []  333.16 181.35 90 top
NOREF#1688  -  []  352.13 244.72 90 top
NOREF#1689  -  []  20.64 483.76 90 top
NOREF#1690  -  []  312.9 249.57 90 top
NOREF#1691  -  []  311.39 250.05 0 top
NOREF#1692  -  []  343.95 233.34 90 top
NOREF#1693  -  []  241.77 273.73 90 top
NOREF#1694  -  []  267.41 133.69 0 top
NOREF#1695  -  []  495.12 176.46 90 top
NOREF#1696  -  []  303.27 235.18 0 top
NOREF#1697  -  []  218.17 209.61 90 top
NOREF#1698  -  []  37.48 483.76 90 top
NOREF#1699  -  []  249.03 276.59 90 top
NOREF#1700  -  []  287.73 484.4 0 top
NOREF#1701  -  []  352.57 246.5 0 top
NOREF#1702  -  []  262.49 297.25 90 top
NOREF#1703  -  []  474 197.59 0 top
NOREF#1704  -  []  335.71 193.56 0 top
NOREF#1705  -  []  528.48 484.08 0 top
NOREF#1706  -  []  229.94 246.91 0 top
NOREF#1707  -  []  349.69 136.26 90 top
NOREF#1708  -  []  310.57 270.84 0 top
NOREF#1709  -  []  314.23 247.83 0 top
NOREF#1710  -  []  87.81 196.06 0 top
NOREF#1711  -  []  352.35 289.79 90 top
NOREF#1712  -  []  229.33 210.27 0 top
NOREF#1713  -  []  487.13 186.81 90 top
NOREF#1714  -  []  263.34 262.36 90 top
NOREF#1715  -  []  346.54 133.3 90 top
NOREF#1716  -  []  270.62 246.5 0 top
NOREF#1717  -  []  375.73 463.08 90 top
NOREF#1718  -  []  215.38 242.3 90 top
NOREF#1719  -  []  349.94 185.61 0 top
NOREF#1720  -  []  272.23 232.39 90 top
NOREF#1721  -  []  269.11 233.64 90 top
NOREF#1722  -  []  458.37 199.87 0 top
NOREF#1723  -  []  350.13 267.46 90 top
NOREF#1724  -  []  344.52 294.3 0 top
NOREF#1725  -  []  355.48 297.35 0 top
NOREF#1726  -  []  487.88 224.41 90 top
NOREF#1727  -  []  295.01 253.56 0 top
NOREF#1728  -  []  147.72 483.84 90 top
NOREF#1729  -  []  271.48 246.02 90 top
NOREF#1730  -  []  267.05 135.09 90 top
NOREF#1731  -  []  475.38 253.51 0 top
NOREF#1732  -  []  313.17 296.17 0 top
NOREF#1733  -  []  350.12 466.58 90 top
NOREF#1734  -  []  493.02 205.99 0 top
NOREF#1735  -  []  95.24 156.45 0 top
NOREF#1736  -  []  83.67 275.75 0 top
NOREF#1737  -  []  220.96 175.55 90 top
NOREF#1738  -  []  341.62 292.95 90 top
NOREF#1739  -  []  345.33 134.7 0 top
NOREF#1740  -  []  255.76 192.32 0 top
NOREF#1741  -  []  84.1 265.34 0 top
NOREF#1742  -  []  255.58 194.22 90 top
NOREF#1743  -  []  261.62 292.95 90 top
NOREF#1744  -  []  273.4 299.38 0 top
NOREF#1745  -  []  350.01 270.51 0 top
NOREF#1746  -  []  296.45 484.08 0 top
NOREF#1747  -  []  340.83 211.63 0 top
NOREF#1748  -  []  306.54 135.09 0 top
NOREF#1749  -  []  254.66 252.79 0 top
NOREF#1750  -  []  251.23 176.59 90 top
NOREF#1751  -  []  308.62 185.61 0 top
NOREF#1752  -  []  357.95 141.12 90 top
NOREF#1753  -  []  312.46 242.42 90 top
NOREF#1754  -  []  305.05 146.58 0 top
NOREF#1755  -  []  247.61 484.4 0 top
NOREF#1756  -  []  234.21 249.57 90 top
NOREF#1757  -  []  303.16 484.4 0 top
NOREF#1758  -  []  350.74 250.05 0 top
NOREF#1759  -  []  224.78 262.58 0 top
NOREF#1760  -  []  310.55 134.62 90 top
NOREF#1761  -  []  359.1 143.77 0 top
NOREF#1762  -  []  231.16 243.72 90 top
NOREF#1763  -  []  294.38 183.29 0 top
NOREF#1764  -  []  270.47 184.57 90 top
NOREF#1765  -  []  230.48 244.57 90 top
NOREF#1766  -  []  223.95 232.42 90 top
NOREF#1767  -  []  47.98 265.88 0 top
NOREF#1768  -  []  551.91 147.59 0 top
NOREF#1769  -  []  241.48 268.37 0 top
NOREF#1770  -  []  335.01 182 0 top
NOREF#1771  -  []  470.13 161.06 0 top
NOREF#1772  -  []  293.99 242.3 90 top
NOREF#1773  -  []  230.75 190.05 0 top
NOREF#1774  -  []  233.3 208.63 90 top
NOREF#1775  -  []  457.43 192.81 0 top
NOREF#1776  -  []  481.53 192.66 90 top
NOREF#1777  -  []  472.43 255.51 0 top
NOREF#1778  -  []  87.91 137.16 0 top
NOREF#1779  -  []  477.58 190.01 0 top
NOREF#1780  -  []  211.64 193.86 90 top
NOREF#1781  -  []  337.83 252.37 0 top
NOREF#1782  -  []  308.03 287 0 top
NOREF#1783  -  []  83.29 154.45 0 top
NOREF#1784  -  []  231.11 297.8 90 top
NOREF#1785  -  []  292.33 242.3 90 top
NOREF#1786  -  []  272.57 246.5 0 top
NOREF#1787  -  []  268.93 268.11 0 top
NOREF#1788  -  []  456.13 224.41 90 top
NOREF#1789  -  []  215.09 206.49 0 top
NOREF#1790  -  []  223.09 234.38 0 top
NOREF#1791  -  []  212.54 254.86 90 top
NOREF#1792  -  []  253.22 250.39 0 top
NOREF#1793  -  []  87.81 164.31 0 top
NOREF#1794  -  []  279.1 142.99 90 top
NOREF#1795  -  []  272.21 184.43 0 top
NOREF#1796  -  []  235.3 190.05 0 top
NOREF#1797  -  []  255.83 199.63 0 top
NOREF#1798  -  []  475.18 256.16 90 top
NOREF#1799  -  []  109.42 228.97 90 top
NOREF#1800  -  []  529.38 483.76 90 top
NOREF#1801  -  []  354.21 249.57 90 top
NOREF#1802  -  []  344.11 467.68 0 top
NOREF#1803  -  []  348.01 174.3 90 top
NOREF#1804  -  []  269.53 241.46 90 top
NOREF#1805  -  []  214.68 243.61 0 top
NOREF#1806  -  []  87.37 258.84 90 top
NOREF#1807  -  []  482.83 161.06 0 top
NOREF#1808  -  []  231.16 186.31 90 top
NOREF#1809  -  []  478.69 197.86 90 top
NOREF#1810  -  []  503.71 229.25 0 top
NOREF#1811  -  []  253.29 253.86 90 top
NOREF#1812  -  []  358.18 484.08 0 top
NOREF#1813  -  []  361.89 483.75 90 top
NOREF#1814  -  []  211.64 182.3 90 top
NOREF#1815  -  []  212.78 179.12 90 top
NOREF#1816  -  []  528.18 484.4 0 top
NOREF#1817  -  []  235.44 194.76 90 top
NOREF#1818  -  []  67.34 265.1 90 top
NOREF#1819  -  []  407.29 484.08 0 top
NOREF#1820  -  []  80 289.71 90 top
NOREF#1821  -  []  268.25 234.12 0 top
NOREF#1822  -  []  278.57 231.63 90 top
NOREF#1823  -  []  226.56 259.8 0 top
NOREF#1824  -  []  91.84 217.95 0 top
NOREF#1825  -  []  403.34 462.48 90 top
NOREF#1826  -  []  265.94 203.76 0 top
NOREF#1827  -  []  303.27 173.14 0 top
NOREF#1828  -  []  490.28 190.01 0 top
NOREF#1829  -  []  227.95 259.98 0 top
NOREF#1830  -  []  268.31 179.21 0 top
NOREF#1831  -  []  44.5 483.76 90 top
NOREF#1832  -  []  111.99 157.25 0 top
NOREF#1833  -  []  210.56 252.32 0 top
NOREF#1834  -  []  350.41 180.16 0 top
NOREF#1835  -  []  239.47 261.5 90 top
NOREF#1836  -  []  316.7 296.96 90 top
NOREF#1837  -  []  236.69 484.08 0 top
NOREF#1838  -  []  458.65 181.13 0 top
NOREF#1839  -  []  388.75 484.4 0 top
NOREF#1840  -  []  232.7 250.05 0 top
NOREF#1841  -  []  264.24 267.14 0 top
NOREF#1842  -  []  352.21 181.15 0 top
NOREF#1843  -  []  348.44 262.36 0 top
NOREF#1844  -  []  111.42 159.47 0 top
NOREF#1845  -  []  102.38 233.93 0 top
NOREF#1846  -  []  99.44 282.49 90 top
NOREF#1847  -  []  540.94 233.23 90 top
NOREF#1848  -  []  333.86 241.35 90 top
NOREF#1849  -  []  112.47 190.27 90 top
NOREF#1850  -  []  234.82 285.62 0 top
NOREF#1851  -  []  386.25 484.08 0 top
NOREF#1852  -  []  109.94 214.75 90 top
NOREF#1853  -  []  310.5 183.72 90 top
NOREF#1854  -  []  107.94 156.45 0 top
NOREF#1855  -  []  215.01 253.56 90 top
NOREF#1856  -  []  95.99 249.7 0 top
NOREF#1857  -  []  306.84 149.01 0 top
NOREF#1858  -  []  268.01 233.3 90 top
NOREF#1859  -  []  104.48 204.4 90 top
NOREF#1860  -  []  291.16 240.15 0 top
NOREF#1861  -  []  253.39 255.18 0 top
NOREF#1862  -  []  83.29 249.7 0 top
NOREF#1863  -  []  333.16 252.91 90 top
NOREF#1864  -  []  371.18 467.63 0 top
NOREF#1865  -  []  269.3 185.85 0 top
NOREF#1866  -  []  86.59 220.75 0 top
NOREF#1867  -  []  158.08 484.32 0 top
NOREF#1868  -  []  286.12 483.75 90 top
NOREF#1869  -  []  256.03 484.4 0 top
NOREF#1870  -  []  110.69 188.85 90 top
NOREF#1871  -  []  263.27 173.14 0 top
NOREF#1872  -  []  353.4 299.38 0 top
NOREF#1873  -  []  335.83 259.63 0 top
NOREF#1874  -  []  313.66 269.1 90 top
NOREF#1875  -  []  338.44 299.07 0 top
NOREF#1876  -  []  102.34 249.7 0 top
NOREF#1877  -  []  335.09 261.99 90 top
NOREF#1878  -  []  253.39 195.18 0 top
NOREF#1879  -  []  254.81 241.35 90 top
NOREF#1880  -  []  493.92 240.61 0 top
NOREF#1881  -  []  308.93 268.11 0 top
NOREF#1882  -  []  229.11 172.64 90 top
NOREF#1883  -  []  275.44 194.76 90 top
NOREF#1884  -  []  308.67 241.94 0 top
NOREF#1885  -  []  235.13 243 0 top
NOREF#1886  -  []  223.83 260.94 0 top
NOREF#1887  -  []  487.13 218.56 90 top
NOREF#1888  -  []  107.94 188.2 0 top
NOREF#1889  -  []  180.33 2.28 90 top
NOREF#1890  -  []  310.13 207.46 90 top
NOREF#1891  -  []  351.19 209.1 90 top
NOREF#1892  -  []  251.82 484.4 0 top
NOREF#1893  -  []  264.52 285.16 90 top
NOREF#1894  -  []  331.02 483.75 90 top
NOREF#1895  -  []  559.34 150.57 0 top
NOREF#1896  -  []  230.5 190.23 90 top
NOREF#1897  -  []  541.61 147.98 0 top
NOREF#1898  -  []  351.94 247.8 0 top
NOREF#1899  -  []  112.42 200.32 90 top
NOREF#1900  -  []  278.48 484.4 0 top
NOREF#1901  -  []  227.56 144.79 90 top
NOREF#1902  -  []  344.42 236.56 0 top
NOREF#1903  -  []  460.48 190.01 0 top
NOREF#1904  -  []  474 134.09 0 top
NOREF#1905  -  []  25.06 484.4 0 top
NOREF#1906  -  []  236.52 134.08 90 top
NOREF#1907  -  []  289.83 203.63 90 top
NOREF#1908  -  []  234.21 189.57 90 top
NOREF#1909  -  []  103.28 234.26 0 top
NOREF#1910  -  []  309.85 184.37 90 top
NOREF#1911  -  []  114.42 139.32 0 top
NOREF#1912  -  []  232.57 244.23 90 top
NOREF#1913  -  []  475.32 176.46 90 top
NOREF#1914  -  []  458.65 168.12 0 top
NOREF#1915  -  []  348.49 136.9 0 top
NOREF#1916  -  []  211.83 206.63 0 top
NOREF#1917  -  []  224.52 290.37 90 top
NOREF#1918  -  []  97.99 157.1 90 top
NOREF#1919  -  []  251.64 193.86 90 top
NOREF#1920  -  []  261.44 483.75 90 top
NOREF#1921  -  []  291.16 176.15 90 top
NOREF#1922  -  []  335.16 191.22 90 top
NOREF#1923  -  []  308.49 136.9 0 top
NOREF#1924  -  []  84.1 263.88 0 top
NOREF#1925  -  []  349.94 186.26 0 top
NOREF#1926  -  []  353.62 183.41 0 top
NOREF#1927  -  []  334.33 484.08 0 top
NOREF#1928  -  []  90.89 246.5 90 top
NOREF#1929  -  []  255.76 252.32 0 top
NOREF#1930  -  []  272.8 187.32 90 top
NOREF#1931  -  []  263.95 172.42 90 top
NOREF#1932  -  []  226.54 135.09 0 top
NOREF#1933  -  []  488.08 253.51 0 top
NOREF#1934  -  []  304.24 207.14 0 top
NOREF#1935  -  []  228.03 287 0 top
NOREF#1936  -  []  335.56 252.47 90 top
NOREF#1937  -  []  98.19 154.45 0 top
NOREF#1938  -  []  274.37 295.53 90 top
NOREF#1939  -  []  344.71 467.08 0 top
NOREF#1940  -  []  343.09 174.38 0 top
NOREF#1941  -  []  468.08 218.56 90 top
NOREF#1942  -  []  272.23 167.99 0 top
NOREF#1943  -  []  159.66 484.08 0 top
NOREF#1944  -  []  232.21 184.43 0 top
NOREF#1945  -  []  30.47 483.76 90 top
NOREF#1946  -  []  305.77 483.75 90 top
NOREF#1947  -  []  213.39 195.18 0 top
NOREF#1948  -  []  358.57 171.63 90 top
NOREF#1949  -  []  352.7 190.05 0 top
NOREF#1950  -  []  356.15 249.57 90 top
NOREF#1951  -  []  80.24 220.75 0 top
NOREF#1952  -  []  308.01 173.3 90 top
NOREF#1953  -  []  234.23 187.83 0 top
NOREF#1954  -  []  102.24 224.64 90 top
NOREF#1955  -  []  229.94 246.26 0 top
NOREF#1956  -  []  398.37 483.75 90 top
NOREF#1957  -  []  351.4 241.59 0 top
NOREF#1958  -  []  280.04 137.42 90 top
NOREF#1959  -  []  112.47 158.52 90 top
NOREF#1960  -  []  333.16 192.91 90 top
NOREF#1961  -  []  229.59 259.88 90 top
NOREF#1962  -  []  354.97 145.37 90 top
NOREF#1963  -  []  570 146.81 90 top
NOREF#1964  -  []  314.97 145.37 90 top
NOREF#1965  -  []  329.83 263.63 90 top
NOREF#1966  -  []  114.42 202.82 0 top
NOREF#1967  -  []  272.23 230.19 90 top
NOREF#1968  -  []  103.16 225.53 0 top
NOREF#1969  -  []  352.45 243.75 90 top
NOREF#1970  -  []  409.55 466.58 90 top
NOREF#1971  -  []  318.57 171.63 90 top
NOREF#1972  -  []  319.59 140.38 90 top
NOREF#1973  -  []  310.16 185.37 90 top
NOREF#1974  -  []  466.83 158.26 0 top
NOREF#1975  -  []  223.27 233.14 0 top
NOREF#1976  -  []  479.53 158.26 0 top
NOREF#1977  -  []  87.81 132.56 0 top
NOREF#1978  -  []  269.04 261.34 90 top
NOREF#1979  -  []  214.42 178.17 90 top
NOREF#1980  -  []  345.44 146.16 90 top
NOREF#1981  -  []  48.16 249.91 0 top
NOREF#1982  -  []  273.11 250.23 90 top
NOREF#1983  -  []  113.09 249.7 0 top
NOREF#1984  -  []  229.94 186.91 0 top
NOREF#1985  -  []  145.63 484.08 0 top
NOREF#1986  -  []  539.65 193.24 0 top
NOREF#1987  -  []  112.42 232.07 90 top
NOREF#1988  -  []  45.61 272.5 0 top
NOREF#1989  -  []  89.64 154.45 0 top
NOREF#1990  -  []  403.08 484.08 0 top
NOREF#1991  -  []  91.64 220.6 90 top
NOREF#1992  -  []  349.61 245.05 0 top
NOREF#1993  -  []  277.95 141.12 90 top
NOREF#1994  -  []  355.33 293.17 0 top
NOREF#1995  -  []  232.22 181.15 0 top
NOREF#1996  -  []  549.06 210.41 90 top
NOREF#1997  -  []  343.27 173.14 0 top
NOREF#1998  -  []  292.33 193.86 90 top
NOREF#1999  -  []  262.95 290.44 90 top
NOREF#2000  -  []  312.46 240.47 90 top
NOREF#2001  -  []  214.66 252.79 0 top
NOREF#2002  -  []  312.13 244.72 90 top
NOREF#2003  -  []  215.76 192.32 0 top
NOREF#2004  -  []  382.53 466.58 90 top
NOREF#2005  -  []  468.83 224.41 90 top
NOREF#2006  -  []  270.82 180.82 90 top
NOREF#2007  -  []  360.92 466.58 90 top
NOREF#2008  -  []  316.23 163.88 90 top
NOREF#2009  -  []  231.27 239.68 90 top
NOREF#2010  -  []  529.58 484.4 0 top
NOREF#2011  -  []  504.91 209.19 90 top
NOREF#2012  -  []  255.16 179.65 90 top
NOREF#2013  -  []  214.29 183.93 0 top
NOREF#2014  -  []  473.18 253.51 0 top
NOREF#2015  -  []  315.91 164.78 0 top
NOREF#2016  -  []  349 181.77 90 top
NOREF#2017  -  []  357.14 141.43 90 top
NOREF#2018  -  []  271.48 245.37 90 top
NOREF#2019  -  []  255.58 242.65 90 top
NOREF#2020  -  []  272.05 241.59 0 top
NOREF#2021  -  []  84.1 289.86 0 top
NOREF#2022  -  []  319.1 143.77 0 top
NOREF#2023  -  []  273.99 268.8 0 top
NOREF#2024  -  []  223.27 292.05 0 top
NOREF#2025  -  []  351.02 245.37 0 top
NOREF#2026  -  []  353.1 190.23 90 top
NOREF#2027  -  []  228.32 239.21 0 top
NOREF#2028  -  []  493.92 174.57 0 top
NOREF#2029  -  []  272.23 172.39 90 top
NOREF#2030  -  []  267.25 233.9 90 top
NOREF#2031  -  []  211.16 180.15 0 top
NOREF#2032  -  []  89.64 249.7 0 top
NOREF#2033  -  []  352.26 241.11 90 top
NOREF#2034  -  []  230.82 240.82 90 top
NOREF#2035  -  []  249.83 263.63 90 top
NOREF#2036  -  []  311.81 241.77 90 top
NOREF#2037  -  []  233.66 209.1 90 top
NOREF#2038  -  []  303.27 233.14 0 top
NOREF#2039  -  []  220.62 297.29 0 top
NOREF#2040  -  []  99.44 268.77 90 top
NOREF#2041  -  []  345.88 235.27 0 top
NOREF#2042  -  []  314.61 298.99 90 top
NOREF#2043  -  []  483.26 235.88 0 top
NOREF#2044  -  []  254.42 238.17 90 top
NOREF#2045  -  []  549.44 238.1 90 top
NOREF#2046  -  []  87.91 168.91 0 top
NOREF#2047  -  []  333.22 178.82 0 top
NOREF#2048  -  []  253.16 252.91 90 top
NOREF#2049  -  []  233.81 243.65 0 top
NOREF#2050  -  []  215.16 251.22 90 top
NOREF#2051  -  []  232.91 178.51 90 top
NOREF#2052  -  []  409.6 483.75 90 top
NOREF#2053  -  []  331.23 236.59 90 top
NOREF#2054  -  []  231.48 186.67 90 top
NOREF#2055  -  []  466.08 160.26 0 top
NOREF#2056  -  []  211.34 183.29 0 top
NOREF#2057  -  []  255.76 240.75 0 top
